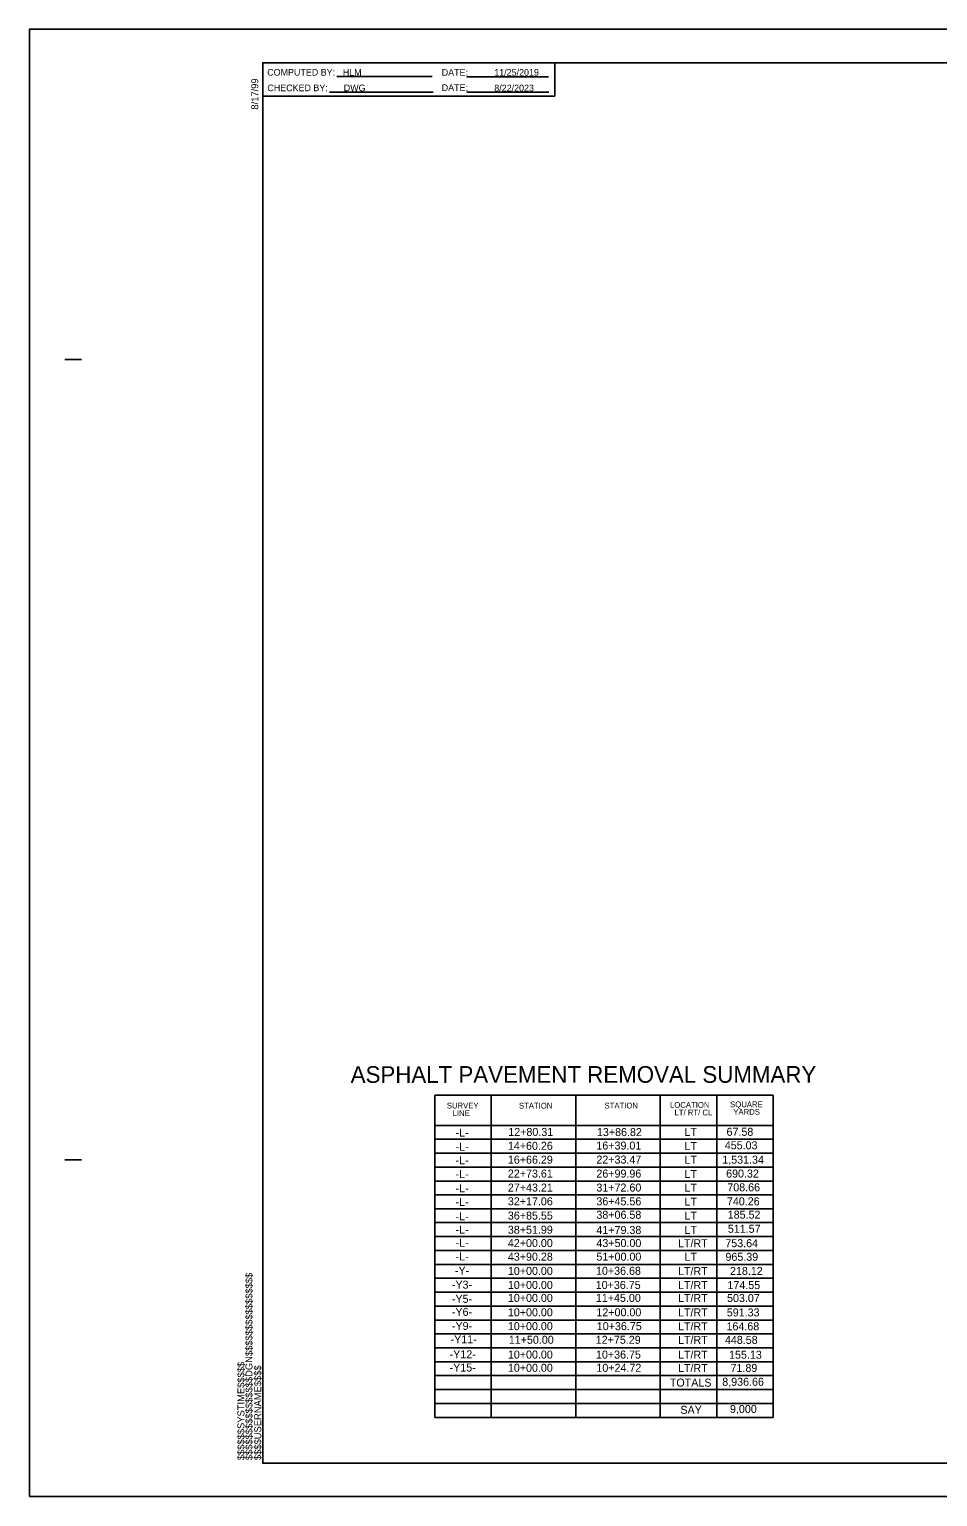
# Model space of a CAD drawing. Extents: x 573680 to 575380, y -53324 to -52224.
# Drawn here: x 573680 to 574361, y -53324 to -52224 of the extents above; entities that cross this region are included whole.
import ezdxf

# ---------------------------------------------------------------- set-up
doc = ezdxf.new("R2010")
doc.units = 0
for name, color, linetype in [('Prop Dimension Text', 7, 'Continuous'), ('Sheet Block System Information CELL', 7, 'Continuous'), ('Sheet Data Field CELL', 7, 'Continuous'), ('Sheet Plan And Profile CELL', 7, 'Continuous'), ('Sheet Plot Border Outside CELL', 7, 'Continuous'), ('Sheet Summary Combination CELL', 7, 'Continuous'), ('Sheet Summary Combination Grid CELL', 7, 'Continuous')]:
    doc.layers.add(name, color=color, linetype=linetype)

msp = doc.modelspace()

# ---------------------------------------------------------------- linework, layer by layer
at = {"layer": 'Sheet Block System Information CELL'}
msp.add_line((573854.9, -53299.3), (573854.9, -53299.3), dxfattribs=at)
at = {"layer": 'Sheet Plan And Profile CELL'}
for p, q in [((573706.4, -52471.8), (573718.9, -52471.8)), ((573706.4, -53071.8), (573718.9, -53071.8)), ((573854.9, -53299.3), (573854.9, -53299.3)), ((573854.9, -53299.3), (573854.9, -53299.3)), ((573854.9, -53299.3), (573854.9, -53299.3)), ((573854.9, -53299.3), (573854.9, -53299.3)), ((573854.9, -53299.3), (573854.9, -53299.3))]:
    msp.add_line(p, q, dxfattribs=at)
msp.add_lwpolyline([(575354.9, -52249.3), (573854.9, -52249.3), (573854.9, -53299.3), (575354.9, -53299.3)], close=True, dxfattribs=at)
at = {"layer": 'Sheet Plot Border Outside CELL'}
msp.add_lwpolyline([(573679.9, -53324.3), (575379.9, -53324.3), (575379.9, -52224.3), (573679.9, -52224.3)], close=True, dxfattribs=at)
at = {"layer": 'Sheet Summary Combination CELL'}
for p, q in [((573910.5, -52259.7), (573982.1, -52259.7)), ((574007.9, -52259.9), (574069.3, -52259.9)), ((573905.1, -52271.4), (573982.8, -52271.4)), ((574008, -52271.4), (574069.4, -52271.4)), ((574111.3, -53023.4), (574111.3, -53023.4)), ((574117, -53023.5), (574117, -53023.5)), ((574125.1, -53023.3), (574125.1, -53023.3)), ((574130.2, -53023.4), (574130.2, -53023.4))]:
    msp.add_line(p, q, dxfattribs=at)
msp.add_lwpolyline([(573854.9, -52249.3), (574073.9, -52249.3), (574073.9, -52274.3), (573854.9, -52274.3)], close=True, dxfattribs=at)
at = {"layer": 'Sheet Summary Combination Grid CELL'}
for p, q in [((573983.9, -53023.4), (574237.8, -53023.4)), ((573983.9, -53023.4), (573983.9, -53264.9)), ((574026.2, -53023.4), (574026.2, -53264.9)), ((574089.7, -53023.4), (574089.7, -53264.9)), ((574153.1, -53023.4), (574153.1, -53264.9)), ((574195.5, -53023.4), (574195.5, -53264.9)), ((574237.8, -53023.4), (574237.8, -53264.9)), ((573983.9, -53046), (574237.8, -53046)), ((573983.9, -53056.4), (574237.8, -53056.4)), ((573983.9, -53066.8), (574237.8, -53066.8)), ((573983.9, -53077.2), (574237.8, -53077.2)), ((573983.9, -53087.7), (574237.8, -53087.7)), ((573983.9, -53098.1), (574237.8, -53098.1)), ((573983.9, -53108.5), (574237.8, -53108.5)), ((573983.9, -53118.9), (574237.8, -53118.9)), ((573983.9, -53129.3), (574237.8, -53129.3)), ((573983.9, -53139.8), (574237.8, -53139.8)), ((573983.9, -53150.2), (574237.8, -53150.2)), ((573983.9, -53160.6), (574237.8, -53160.6)), ((573983.9, -53171), (574237.8, -53171)), ((573983.9, -53181.5), (574237.8, -53181.5)), ((573983.9, -53191.9), (574237.8, -53191.9)), ((573983.9, -53202.3), (574237.8, -53202.3)), ((573983.9, -53212.7), (574237.8, -53212.7)), ((573983.9, -53223.2), (574237.8, -53223.2)), ((573983.9, -53233.6), (574237.8, -53233.6)), ((573983.9, -53244), (574237.8, -53244)), ((573983.9, -53254.4), (574237.8, -53254.4)), ((573983.9, -53264.9), (574237.8, -53264.9))]:
    msp.add_line(p, q, dxfattribs=at)

# ---------------------------------------------------------------- texts
at = {"layer": 'Prop Dimension Text'}
for s, p in [('-L-', (573999.6, -53054.4)), ('12+80.31', (574039.1, -53053.9)), ('13+86.82', (574105.6, -53054)), ('LT', (574171.3, -53053.9)), ('67.58', (574202.8, -53053.8)), ('-L-', (573999.6, -53065)), ('14+60.26', (574038.8, -53064.3)), ('16+39.01', (574105.2, -53064.1)), ('LT', (574171.3, -53064.5)), ('455.03', (574201.5, -53063.9)), ('-L-', (573999.6, -53075.2)), ('16+66.29', (574038.8, -53074.7)), ('22+33.47', (574105.2, -53074.6)), ('LT', (574171.3, -53074.8)), ('1,531.34', (574199.6, -53074.7)), ('-L-', (573999.6, -53085.5)), ('22+73.61', (574038.8, -53085.1)), ('26+99.96', (574105.2, -53085.1)), ('LT', (574171.3, -53085.4)), ('690.32', (574202.5, -53085.1)), ('-L-', (573999.6, -53096.1)), ('27+43.21', (574038.8, -53095.6)), ('31+72.60', (574105.2, -53095.6)), ('LT', (574171.3, -53095.7)), ('708.66', (574203.4, -53095.4)), ('-L-', (573999.6, -53106.4)), ('32+17.06', (574038.8, -53105.9)), ('36+45.56', (574105.2, -53105.9)), ('LT', (574171.3, -53106.2)), ('740.26', (574203.1, -53105.9)), ('-L-', (573999.6, -53117.2)), ('36+85.55', (574038.8, -53116.6)), ('38+06.58', (574105.2, -53116)), ('LT', (574171.3, -53116.7)), ('185.52', (574203.7, -53115.9)), ('-L-', (573999.6, -53127.1)), ('38+51.99', (574038.8, -53127.2)), ('41+79.38', (574105.2, -53127.4)), ('LT', (574171.3, -53127.3)), ('511.57', (574203.8, -53126.5)), ('-L-', (573999.6, -53137)), ('42+00.00', (574038.8, -53137.2)), ('43+50.00', (574105.2, -53137.2)), ('LT/RT', (574166.4, -53137.3)), ('753.64', (574201.9, -53137.3)), ('-Y-', (573999.1, -53157.8)), ('-L-', (573999.6, -53147.2)), ('43+90.28', (574038.8, -53147.4)), ('10+00.00', (574038.8, -53158.1)), ('51+00.00', (574105.2, -53147.4)), ('10+36.68', (574104.9, -53158)), ('LT/RT', (574166.4, -53158.2)), ('LT', (574171.3, -53147.5)), ('965.39', (574202, -53147.5)), ('-Y3-', (573996.8, -53168.4)), ('10+00.00', (574038.8, -53168.6)), ('10+36.75', (574104.7, -53168.6)), ('LT/RT', (574166.4, -53168.7)), ('174.55', (574203.5, -53168.7)), ('218.12', (574205.4, -53158.1)), ('-Y5-', (573996.8, -53179)), ('10+00.00', (574038.8, -53178.3)), ('11+45.00', (574104.8, -53178.3)), ('LT/RT', (574166.4, -53178.4)), ('503.07', (574203.2, -53178.4)), ('-Y6-', (573996.8, -53188.8)), ('10+00.00', (574038.8, -53189.1)), ('12+00.00', (574105.2, -53189.1)), ('LT/RT', (574166.4, -53189.2)), ('591.33', (574203, -53189.2)), ('-Y9-', (573996.8, -53199.3)), ('10+00.00', (574038.8, -53199.5)), ('10+36.75', (574105.5, -53199.5)), ('LT/RT', (574166.4, -53199.6)), ('164.68', (574202.8, -53199.6)), ('-Y11-', (573995.8, -53209.4)), ('11+50.00', (574039.5, -53209.7)), ('12+75.29', (574104.7, -53209.7)), ('LT/RT', (574166.4, -53209.8)), ('448.58', (574201.6, -53209.8)), ('-Y12-', (573995.1, -53220.6)), ('10+00.00', (574038.8, -53220.8)), ('10+36.75', (574104.9, -53220.8)), ('LT/RT', (574166.4, -53220.9)), ('155.13', (574204.7, -53220.9)), ('-Y15-', (573995.1, -53230.5)), ('10+00.00', (574038.8, -53230.7)), ('10+24.72', (574105.2, -53230.7)), ('LT/RT', (574166.4, -53230.9)), ('71.89', (574205.8, -53230.8)), ('TOTALS', (574160.3, -53241.8)), ('8,936.66', (574199.6, -53241.2)), ('SAY', (574168.2, -53262.2)), ('9,000', (574205.4, -53261.6))]:
    msp.add_text(s, height=6, dxfattribs=at).set_placement(p)
at = {"layer": 'Sheet Block System Information CELL'}
for s, p in [('$$$$$$$$$$$$$$$$DGN$$$$$$$$$$$$$$$$', (573847.2, -53297)), ('$$$$$$SYSTIME$$$$$', (573841.2, -53297)), ('$$$$USERNAME$$$$', (573853.8, -53296.9))]:
    msp.add_text(s, height=5.25, rotation=90, dxfattribs=at).set_placement(p)
at = {"layer": 'Sheet Data Field CELL'}
for s, p in [('HLM', (573915, -52259)), ('11/25/2019', (574028.6, -52259.1)), ('DWG', (573915.7, -52270.7)), ('8/22/2023', (574028.6, -52270.8))]:
    msp.add_text(s, height=5, dxfattribs=at).set_placement(p)
at = {"layer": 'Sheet Plan And Profile CELL'}
msp.add_text('8/17/99', height=5.25, rotation=90, dxfattribs=at).set_placement((573851.6, -52284.5))
at = {"layer": 'Sheet Summary Combination CELL'}
for s, height, p in [('COMPUTED BY:', 5, (573858.3, -52259)), ('DATE:', 5, (573989.2, -52259.1)), ('CHECKED BY:', 5, (573858.4, -52270.7)), ('DATE:', 5, (573989.2, -52270.5)), ('SURVEY', 4.33, (573993, -53033.3)), ('STATION', 4.33, (574047.1, -53033.4)), ('STATION', 4.33, (574111.3, -53033.3)), ('LOCATION', 4.33, (574160.4, -53032.8)), ('LINE', 4.33, (573997.4, -53039)), ('LT/ RT/ CL', 4.33, (574163.8, -53038.5))]:
    msp.add_text(s, height=height, dxfattribs=at).set_placement(p)
msp.add_text('ASPHALT PAVEMENT REMOVAL SUMMARY', height=12.5, rotation=0.0119, dxfattribs=at).set_placement((573920.9, -53014.1))
at = {"layer": 'Sheet Summary Combination Grid CELL'}
for s, p in [('SQUARE', (574205.5, -53032.4)), ('YARDS', (574207.9, -53038))]:
    msp.add_text(s, height=4.33, dxfattribs=at).set_placement(p)

doc.saveas('drawing.dxf')
